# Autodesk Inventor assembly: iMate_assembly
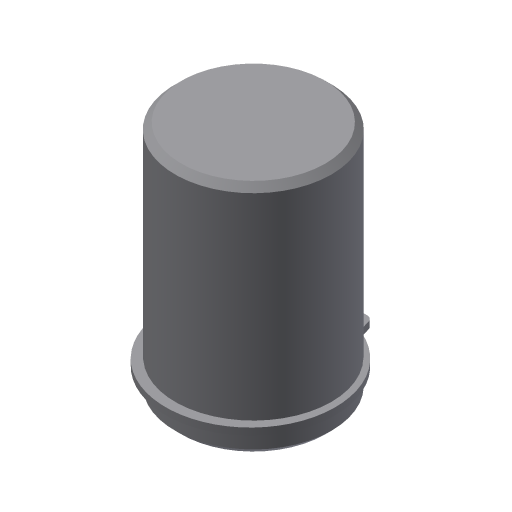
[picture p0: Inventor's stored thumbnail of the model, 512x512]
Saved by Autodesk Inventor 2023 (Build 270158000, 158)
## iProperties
Created: 2016-08
Part Number: iMate_assembly
Document SubType Name: Assembly
Designer: Sandeep
Author: Sandeep
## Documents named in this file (3)
- D:\PROJECTS\Project 2022\Autodesk Inventor For Professional 2023\RESOURCES INVENTOR 2023\RESOURCES INVENTOR 2023\Inventor_2023_tut\Inventor_2023_tut\c17_Inv_2023_tut\c17_tut02\iMate_assembly.iam
- D:\PROJECTS\Project 2022\Autodesk Inventor For Professional 2023\RESOURCES INVENTOR 2023\RESOURCES INVENTOR 2023\Inventor_2023_tut\Inventor_2023_tut\c17_Inv_2023_tut\c17_tut02\Shaft.ipt
- D:\PROJECTS\Project 2022\Autodesk Inventor For Professional 2023\RESOURCES INVENTOR 2023\RESOURCES INVENTOR 2023\Inventor_2023_tut\Inventor_2023_tut\c17_Inv_2023_tut\c17_tut02\circlip.ipt
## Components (2 placed, 2 different names)
1. Shaft:1
2. circlip:1
